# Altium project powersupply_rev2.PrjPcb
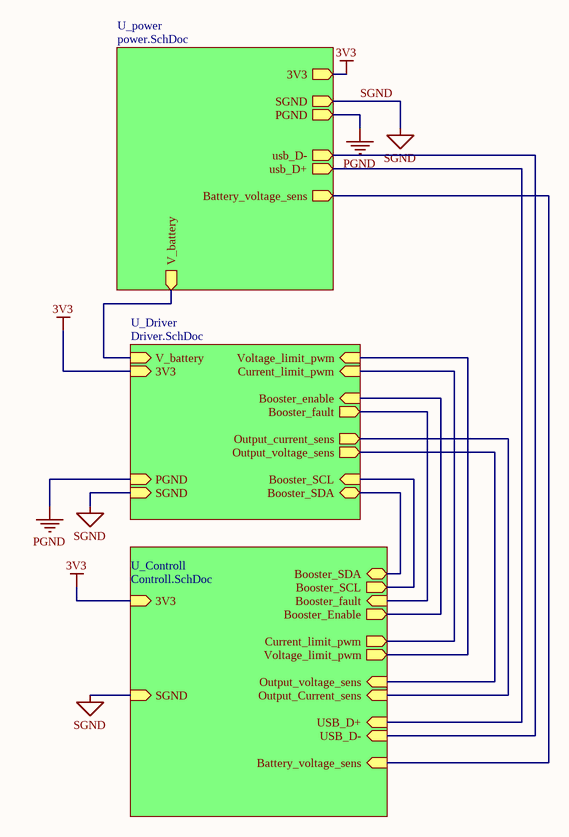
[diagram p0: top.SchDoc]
16 sheets, 137 parts. Net scope: strictly hierarchical (ports join the sheet entries above them; power ports are local).
Board file: PCB1.PcbDoc
Sheets:
  top.SchDoc
    U_power = power.SchDoc
      LDO = LDO.SchDoc
      Battery = battery.SchDoc
      U_usb = usb.SchDoc
      U_usb_isolator = usb_isolator.SchDoc
    U_Driver = Driver.SchDoc
      U_Booster = Booster.SchDoc
      U_linear_regulator = linear_regulator.SchDoc
      pta_current = pwm_to_analog.SchDoc
      pta_voltage = pwm_to_analog_w_gain.SchDoc
    U_Controll = Controll.SchDoc
      U_knobs = knobs.SchDoc
      U_mcu = mcu.SchDoc
      U_Display = Display.SchDoc
      U_programmer = programmer.SchDoc

## Sheet top.SchDoc
size A3

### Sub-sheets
U_Controll = Controll.SchDoc: 3V3 (in), SGND (in), Booster_fault (in), Booster_Enable (out), Voltage_limit_pwm (out), Current_limit_pwm (out), USB_D+ (in), USB_D- (in), Battery_voltage_sens (in), Output_voltage_sens (in), Output_Current_sens (in), Booster_SDA (bidir), Booster_SCL (out)
U_Driver = Driver.SchDoc: V_battery (in), SGND (in), PGND (in), 3V3 (in), Voltage_limit_pwm (in), Current_limit_pwm (in), Booster_enable (in), Output_current_sens (out), Output_voltage_sens (out), Booster_SCL (in), Booster_SDA (bidir), Booster_fault (out)
U_power = power.SchDoc: usb_D- (out), usb_D+ (out), 3V3 (out), SGND (out), PGND (out), V_battery (out), Battery_voltage_sens (out)

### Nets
3V3: sheet U_power/3V3, sheet U_Driver/3V3, sheet U_Controll/3V3
PGND: sheet U_power/PGND, sheet U_Driver/PGND
SGND: sheet U_power/SGND, sheet U_Driver/SGND, sheet U_Controll/SGND
VBAT: sheet U_power/V_battery, sheet U_Driver/V_battery
NetR4_1: sheet U_power/Battery_voltage_sens, sheet U_Controll/Battery_voltage_sens
NetR7_1: sheet U_Driver/Booster_SCL, sheet U_Controll/Booster_SCL
NetR8_1: sheet U_Driver/Booster_SDA, sheet U_Controll/Booster_SDA
NetR9_1: sheet U_Driver/Booster_enable, sheet U_Controll/Booster_Enable
NetR21_1: sheet U_Driver/Current_limit_pwm, sheet U_Controll/Current_limit_pwm
NetR29_2: sheet U_power/usb_D+, sheet U_Controll/USB_D+
NetR31_2: sheet U_power/usb_D-, sheet U_Controll/USB_D-
NetR32_1: sheet U_Driver/Output_voltage_sens, sheet U_Controll/Output_voltage_sens
NetR49_1: sheet U_Driver/Voltage_limit_pwm, sheet U_Controll/Voltage_limit_pwm
NetU1_25: sheet U_Driver/Output_current_sens, sheet U_Controll/Output_Current_sens
NetU1_45: sheet U_Driver/Booster_fault, sheet U_Controll/Booster_fault

## Sheet power.SchDoc
size A3
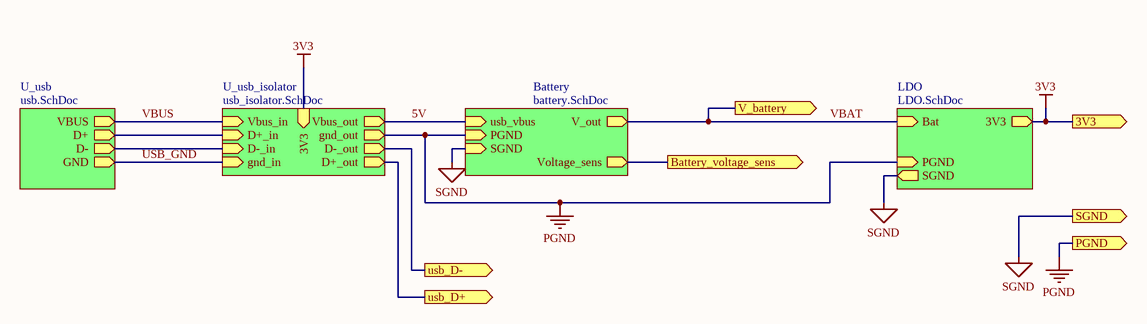
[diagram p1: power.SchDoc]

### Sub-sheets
Battery = battery.SchDoc: V_out (out), Voltage_sens (out), usb_vbus (in), PGND (in), SGND (in)
LDO = LDO.SchDoc: Bat (in), PGND (in), 3V3 (out), SGND (out)
U_usb = usb.SchDoc: VBUS (out), GND (out), D+ (out), D- (out)
U_usb_isolator = usb_isolator.SchDoc: Vbus_in (in), D+_in (in), D-_in (in), gnd_in (in), gnd_out (out), D-_out (out), D+_out (out), Vbus_out (out), 3V3 (in)

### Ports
3V3 (out), Battery_voltage_sens (out), PGND (out), SGND (out), usb_D+ (out), usb_D- (out), V_battery (out)

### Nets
3V3: port 3V3, sheet LDO/3V3, sheet U_usb_isolator/3V3
PGND: port PGND, sheet LDO/PGND, sheet Battery/PGND, sheet U_usb_isolator/gnd_out
SGND: port SGND, sheet LDO/SGND, sheet Battery/SGND
5V: sheet Battery/usb_vbus, sheet U_usb_isolator/Vbus_out
USB_GND: sheet U_usb/GND, sheet U_usb_isolator/gnd_in
VBAT: port V_battery, sheet LDO/Bat, sheet Battery/V_out
VBUS: sheet U_usb/VBUS, sheet U_usb_isolator/Vbus_in
NetJ1_A6: sheet U_usb/D+, sheet U_usb_isolator/D+_in
NetJ1_A7: sheet U_usb/D-, sheet U_usb_isolator/D-_in
NetR4_1: port Battery_voltage_sens, sheet Battery/Voltage_sens
NetR29_2: port usb_D+, sheet U_usb_isolator/D+_out
NetR31_2: port usb_D-, sheet U_usb_isolator/D-_out

## Sheet LDO.SchDoc
size A4
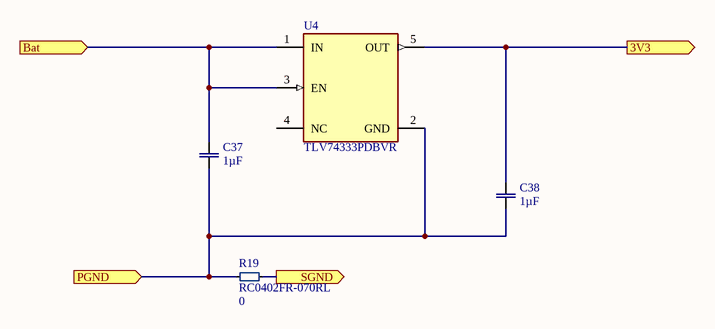
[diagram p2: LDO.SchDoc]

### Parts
C37  Capacitance: 1µF  [CAP0805]  (hidden comment: CL21B105KBFNNNG)
C38  Capacitance: 1µF  [CAP0805]  (hidden comment: CL21B105KBFNNNG)
R19  RC0402FR-070RL  Resistance: 0  [SMD_0402(1005)_M]
U4  TLV74333PDBVR  [FP-DBV0005A-IPC_A]

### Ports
3V3 (out), Bat (in), PGND (in), SGND (out)

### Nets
3V3: C38.2 U4.5(OUT) ; port 3V3
PGND: C37.1 C38.1 R19.1 U4.2(GND) ; port PGND
SGND: R19.2 ; port SGND
VBAT: C37.2 U4.1(IN) U4.3(EN) ; port Bat

Not connected (* = marked no-connect by the designer): U4 4(NC)

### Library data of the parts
C37 C38 = CMP-0001-00012-4: SAMSUNG ELECTRO-MECHANICS - CL21B105KBFNNNG - MLCC CAPACITORS; Voltage Rating: 50V; Dielectric: X7R; Material: Ceramic; Tolerance: 10%
R19 = CMP-0001-00005-6: Res Thick Film 0402 0 Ohm Molded SMD SMD Paper T/R; Value: 0; Temperature Coefficient: 200ppm/°C; Power Rating: 62.5mW; Voltage Rating: 50V; Tolerance: 1%
U4 = CMP-00004-1: 300mA Low-Dropout (LDO) Regulator 5-SOT-23 -40 to 125; Power Supply Rejection Ratio (PSRR): 28dB; Dropout Voltage: 270mV; Min Output Voltage: 3.3V; Output Configuration: Positive; Max Input Voltage: 5.5V; Output Type: Fixed; Number of Regulators: 1; Quiescent Current: 60uA

## Sheet battery.SchDoc
size A4
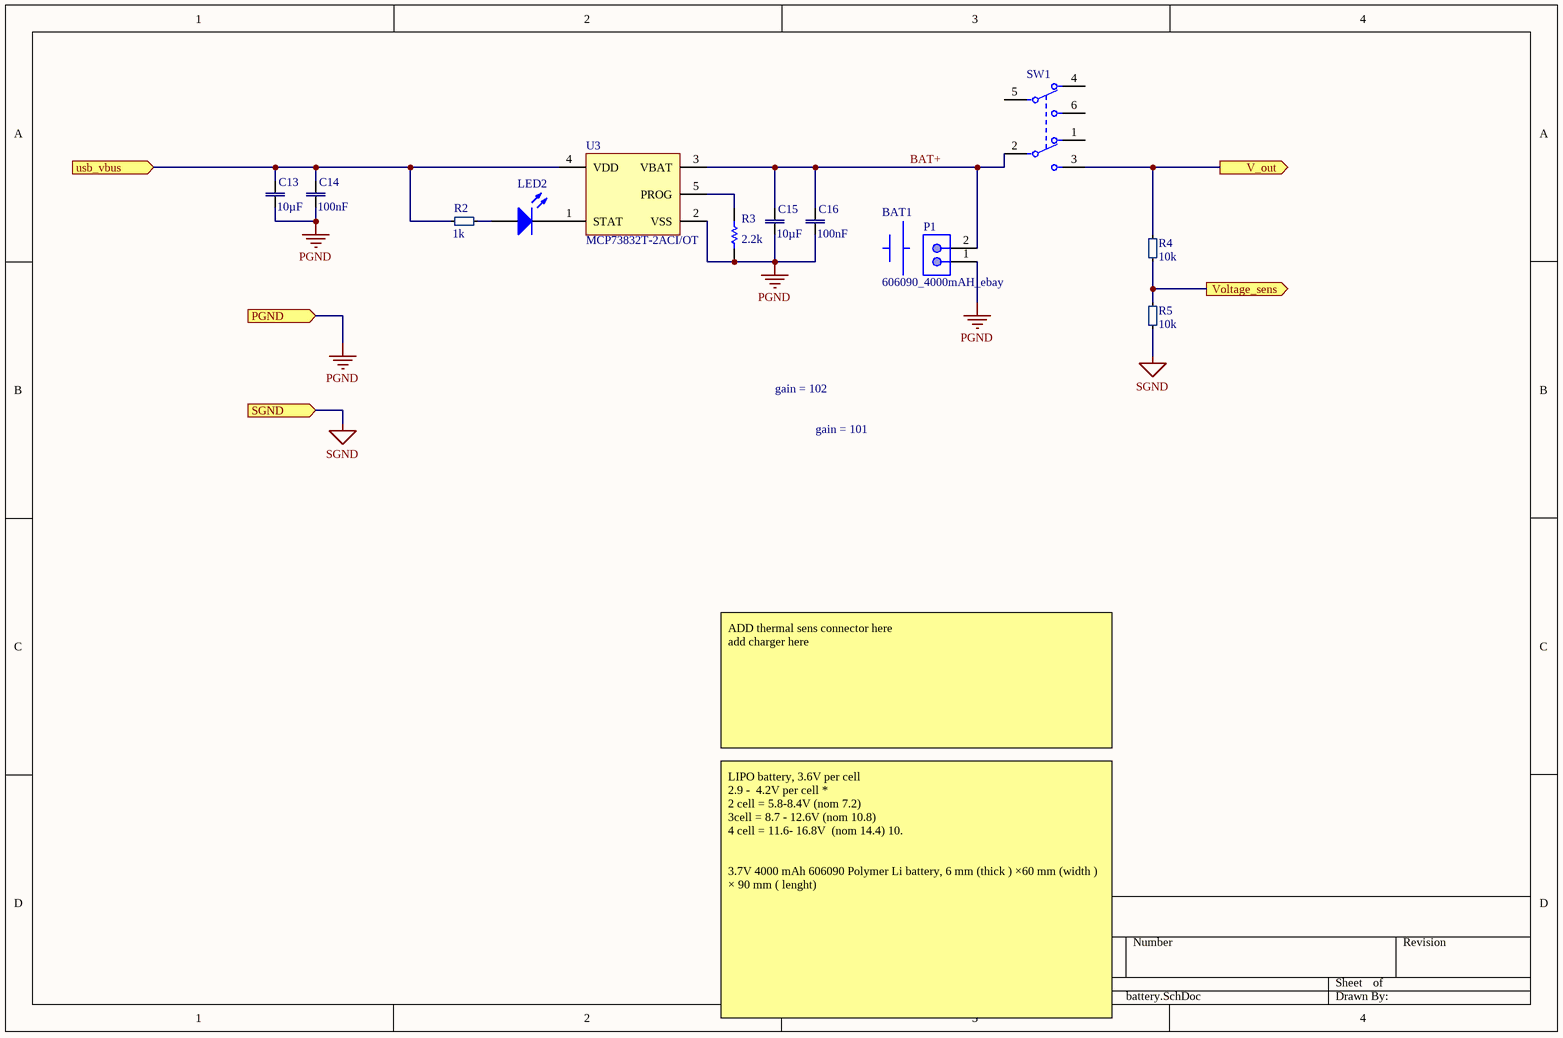
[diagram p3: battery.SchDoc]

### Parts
BAT1  606090_4000mAH_ebay  [606090_4000mAH_ebay-Footprint-1]
C13  Capacitance: 10µF  [Chip2PinSM127P600-8N]  (hidden comment: CL31A106MBHNNNE)
C14  Capacitance: 100nF  [cap0402]  (hidden comment: GRM155R71H104ME14D)
C15  Capacitance: 10µF  [Chip2PinSM127P600-8N]  (hidden comment: CL31A106MBHNNNE)
C16  Capacitance: 100nF  [cap0402]  (hidden comment: GRM155R71H104ME14D)
LED2  150080BS75000  [0805_A]  (value not drawn)
P1  B2B-XH-A(LF)(SN)  [JST-B2B-XH-A_V]  (value not drawn)
R2  Resistance: 1k  [SMD_0402(1005)_M]  (hidden comment: RC0402FR-071KL)
R3  Resistance: 2.2k  [RESC1005X40X25NL05T10]  (hidden comment: RC0402FR-072K2L)
R4  Resistance: 10k  [SMD_0402(1005)_M]  (hidden comment: RC0402FR-0710KL)
R5  Resistance: 10k  [SMD_0402(1005)_M]  (hidden comment: RC0402FR-0710KL)
SW1  100DP1T2B3M2QEH  [FP-100DP1T2B3M2QEH-MFG]  (value not drawn)
U3  MCP73832T-2ACI/OT  [SOT-23-OT5_M]

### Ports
PGND (in), SGND (in), usb_vbus (in), V_out (out), Voltage_sens (out)

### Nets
PGND: C13.1 C14.1 C15.1 C16.1 P1.1 R3.1 U3.2(VSS) ; port PGND
SGND: R5.1 ; port SGND
5V: C13.2 C14.2 R2.2 U3.4(VDD) ; port usb_vbus
BAT+: C15.2 C16.2 P1.2 SW1.2 U3.3(VBAT)
VBAT: R4.2 SW1.3 ; port V_out
NetLED2_1: LED2.1(K) U3.1(STAT)
NetLED2_2: LED2.2(A) R2.1
NetR3_2: R3.2 U3.5(PROG)
NetR4_1: R4.1 R5.2 ; port Voltage_sens

Not connected (* = marked no-connect by the designer): SW1 1 4 5 6

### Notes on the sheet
- gain = 102
- gain = 101
- ADD thermal sens connector here
  add charger here
- LIPO battery, 3.6V per cell
  2.9 -  4.2V per cell *
  2 cell = 5.8-8.4V (nom 7.2)
  3cell = 8.7 - 12.6V (nom 10.8)
  4 cell = 11.6- 16.8V  (nom 14.4) 10.
  3.7V 4000 mAh 606090 Polymer Li battery, 6 mm (thick ) ×60 mm (width ) × 90 mm ( lenght)

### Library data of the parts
BAT1 = CMP-ROOT-00019-4: https://www.ebay.com/itm/3-7V-4000-mAh-606090-Polymer-Li-battery-Li-po-For-PDA-GPS-DVD-ipod-Tablet-PC/182107148013; Voltage: 3.7V
C13 C15 = CMP-0001-00015-2: CAP CER 10UF 50V X5R 1206; Capacitor Type: Ceramic; Tolerance: 20%
C14 C16 = CMP-0001-00001-8: 0402 0.1 uF 50 V ±20% Tolerance X7R SMT Monolithic Ceramic Chip Capacitor; Value: 100nF; Voltage Rating: 50V
LED2 = CMP-00002-1: SMD LED blue 3.5 V 0805, 150080BS75000, Würth Elektronik; Dominant Wavelength: 470nm; Luminous Intensity: 145mcd; Lens Style: Clear,Rectangular; Forward Current: 30mA; Test Current: 20mA; Forward Voltage: 3.2V; Viewing Angle: 140°
P1 = CMP-ROOT-00008-1: Conn Shrouded Header (4 Sides) HDR 2 POS 2.5mm Solder ST Thru-Hole Box; Max Current Rating: 3A; Connector Type: Male Pin; Contact Resistance: 20mR; Max Voltage Rating (DC): 250V; System: Connector; Wire/Cable Gauge: 22AWG; Number of Contacts: 2; Insulation Resistance: 1GR
R2 = CMP-001-0000-7: Surface Mount Chip Resistor, Thick Film, RC Series, 1 kohm, 62.5 mW, 1%, 50 V, 0402 [1005 Metric]; Temperature Coefficient: 100ppm/°C; Value: 1k; Voltage Rating: 50V; Power Rating: 62.5mW
R3 = CMP-001-0020-3: RES SMD 2.2K OHM 1% 1/16W 0402; Temperature Coefficient: 100ppm/°C; Voltage Rating: 50V; Power Rating: 63mW
R4 R5 = CMP-008-0005-9: Surface Mount Thick Film Resistor, Rc Series, 10 Kohm, 62.5 Mw, - 1%, 50 V, 0402 [1005 Metric]; Voltage Rating (DC): 50V; Value: 10k; Temperature Coefficient: 100ppm/°C; Power Rating: 62.5mW
SW1 = CMP-ROOT-00014-1: 100 Series DPDT On-None-On Through Hole Miniature Toggle Switch; Illumination Type: Non-Illuminated; Actuator Type: Standard Round; Switch Function: On-On; Actuator Length: 6.86mm; Voltage Rating (AC): 120V; Actuator Material: Brass,Chrome; Current Rating: 5A; Voltage Rating (DC): 28V; Electrical Life: 40000Cycles
U3 = CMP-006-0003-2: BATTERY CHARGER, 500mA, SOT23-5; Battery Type:Li-Ion, Li-Pol; Input Voltage:6V; Battery Charge Voltage:4.2V; Charge Current Max:500mA; Battery IC Case Style:SOT-23; No. of Pins:5; No. of Series Cells:1; Operating Temperature Max:85 C; Max Supply Voltage: 6V; Number of Cells: 1; Max Output Voltage: 4.5V; Max Power Dissipation: 1.54W; Min Supply Voltage: 3.75V; Min Output Voltage: 4.168V; Output Current: 10mA; Output Voltage: 4.2V

## Sheet usb.SchDoc
size A3
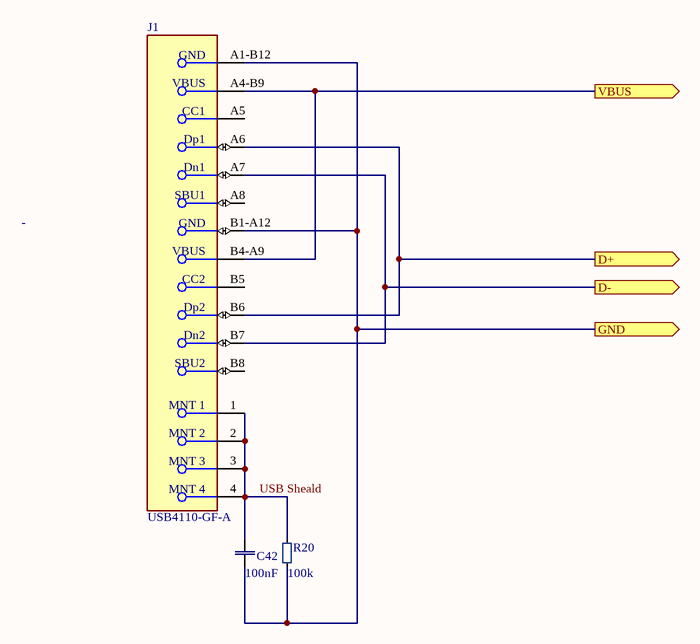
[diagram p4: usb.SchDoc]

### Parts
C42  Capacitance: 100nF  [cap0402]  (hidden comment: GRM155R71H104ME14D)
J1  USB4110-GF-A  [FP-USB4110-GF-A-MFG]
R20  Resistance: 100k  [SMD_0402(1005)_M]  (hidden comment: RC0402FR-07100KL)

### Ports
D+ (out), D- (out), GND (out), VBUS (out)

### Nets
USB Sheald: C42.2 J1.1(MNT_1) J1.2(MNT_2) J1.3(MNT_3) J1.4(MNT_4) R20.2
USB_GND: C42.1 J1.A1-B12(GND) J1.B1-A12(GND) R20.1 ; port GND
VBUS: J1.A4-B9(VBUS) J1.B4-A9(VBUS) ; port VBUS
NetJ1_A6: J1.A6(Dp1) J1.B6(Dp2) ; port D+
NetJ1_A7: J1.A7(Dn1) J1.B7(Dn2) ; port D-

Not connected (* = marked no-connect by the designer): J1 A5(CC1) A8(SBU1) B5(CC2) B8(SBU2)

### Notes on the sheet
- -

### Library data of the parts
C42 = CMP-0001-00001-8: as C14 on sheet battery
J1 = CMP-ROOT-00018-1: Conn Usb 2.0 Type-c R/a SMT; Number of Positions: 12; System: Connector
R20 = CMP-0001-00006-4: Res General Purpose Thick Film 0402 100K Ohm 1% 1/16W ±100ppm/°C Molded SMD Paper T/R; Max Power Dissipation: 63mW; Voltage Rating: 50V

## Sheet usb_isolator.SchDoc
size A3
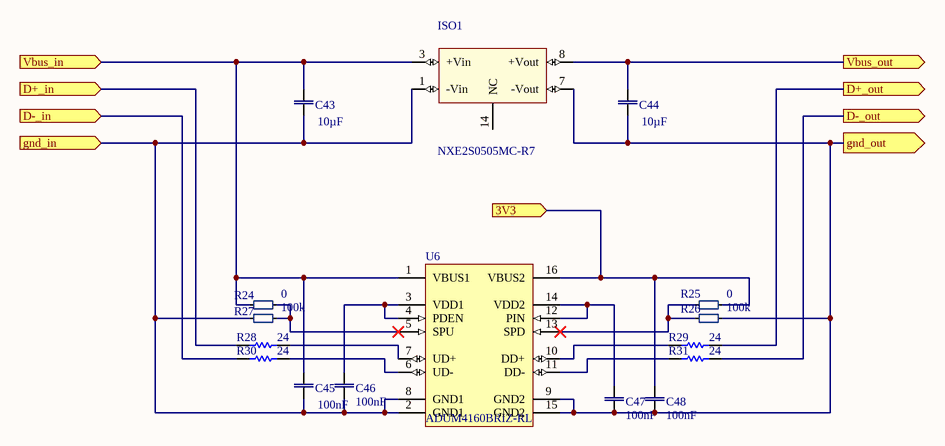
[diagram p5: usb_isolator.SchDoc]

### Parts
C43  Capacitance: 10µF  [Chip2PinSM127P600-8N]  (hidden comment: CL31A106MBHNNNE)
C44  Capacitance: 10µF  [Chip2PinSM127P600-8N]  (hidden comment: CL31A106MBHNNNE)
C45  Capacitance: 100nF  [cap0402]  (hidden comment: GRM155R71H104ME14D)
C46  Capacitance: 100nF  [cap0402]  (hidden comment: GRM155R71H104ME14D)
C47  Capacitance: 100nF  [cap0402]  (hidden comment: GRM155R71H104ME14D)
C48  Capacitance: 100nF  [cap0402]  (hidden comment: GRM155R71H104ME14D)
ISO1  NXE2S0505MC-R7  [NXE2S0505MC-R7-Footprint-1]
R24  Resistance: 0  [SMD_0402(1005)_M]  (hidden comment: RC0402FR-070RL)
R25  Resistance: 0  [SMD_0402(1005)_M]  (hidden comment: RC0402FR-070RL)
R26  Resistance: 100k  [SMD_0402(1005)_M]  (hidden comment: RC0402FR-07100KL)
R27  Resistance: 100k  [SMD_0402(1005)_M]  (hidden comment: RC0402FR-07100KL)
R28  Resistance: 24  [RESC1005X40X25ML05T10]  (hidden comment: RC0402FR-0724RL)
R29  Resistance: 24  [RESC1005X40X25ML05T10]  (hidden comment: RC0402FR-0724RL)
R30  Resistance: 24  [RESC1005X40X25ML05T10]  (hidden comment: RC0402FR-0724RL)
R31  Resistance: 24  [RESC1005X40X25ML05T10]  (hidden comment: RC0402FR-0724RL)
U6  ADUM4160BRIZ-RL  [ADI-RI-16-1_M]

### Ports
3V3 (in), D+_in (in), D+_out (out), D-_in (in), D-_out (out), gnd_in (in), gnd_out (out), Vbus_in (in), Vbus_out (out)

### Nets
3V3: C48.1 R25.2 U6.16(VBUS2) ; port 3V3
PGND: C44.1 C47.2 C48.2 ISO1.7(-Vout) R26.2 U6.9(GND2) U6.15(GND2) ; port gnd_out
5V: C44.2 ISO1.8(+Vout) ; port Vbus_out
USB_GND: C43.1 C45.1 C46.2 ISO1.1(-Vin) R27.1 U6.2(GND1) U6.8(GND1) ; port gnd_in
VBUS: C43.2 C45.2 ISO1.3(+Vin) R24.1 U6.1(VBUS1) ; port Vbus_in
NetC46_1: C46.1 U6.3(VDD1) U6.4(PDEN)
NetC47_1: C47.1 U6.12(PIN) U6.14(VDD2)
NetJ1_A6: R28.1 ; port D+_in
NetJ1_A7: R30.1 ; port D-_in
NetR24_2: R24.2 R27.2 U6.5(SPU)
NetR25_1: R25.1 R26.1 U6.13(SPD)
NetR28_2: R28.2 U6.7(UD+)
NetR29_1: R29.1 U6.10(DD+)
NetR29_2: R29.2 ; port D+_out
NetR30_2: R30.2 U6.6(UD-)
NetR31_1: R31.1 U6.11(DD-)
NetR31_2: R31.2 ; port D-_out

Not connected (* = marked no-connect by the designer): ISO1 14(NC)

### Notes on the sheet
- Select highspeed or lowspeed

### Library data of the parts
C43 C44 = CMP-0001-00015-2: as C13 on sheet battery
C45-C48 = CMP-0001-00001-8: as C14 on sheet battery
ISO1 = CMP-018-0000-2: DC DC CONVERTER 5V 2W; Current - Output 1: 400mA; Min Input Voltage: 4.5V; Max Input Voltage (DC): 5.5V; Efficiency: 72%; Number of Outputs: 1; Isolation Voltage: 3kV
R24 R25 = CMP-0001-00005-6: as R19 on sheet LDO
R26 R27 = CMP-0001-00006-4: Res General Purpose Thick Film 0402 100K Ohm 1% 1/16W ±100ppm/°C Molded SMD Paper T/R; Power Rating: 63mW; Voltage Rating: 50V
R28-R31 = CMP-0001-00017-2: Thick Film Resistors 24 OHM 1%; Voltage Rating: 50V; Temperature Coefficient: 100ppm/°C; Power Rating: 63mW
U6 = CMP-00003-5: Digital Isolator CMOS 4-CH 12Mbps 16-Pin SOIC T/R; Turn-On Delay Time: 60ns; Channel Type: Bidirectional; Isolated Power: No; Min Supply Voltage: 3.1V; Max Supply Voltage: 5.5V; Nominal Supply Current: 6mA; Propagation Delay: 70ns; Number of Channels: 2

## Sheet Driver.SchDoc
size A3
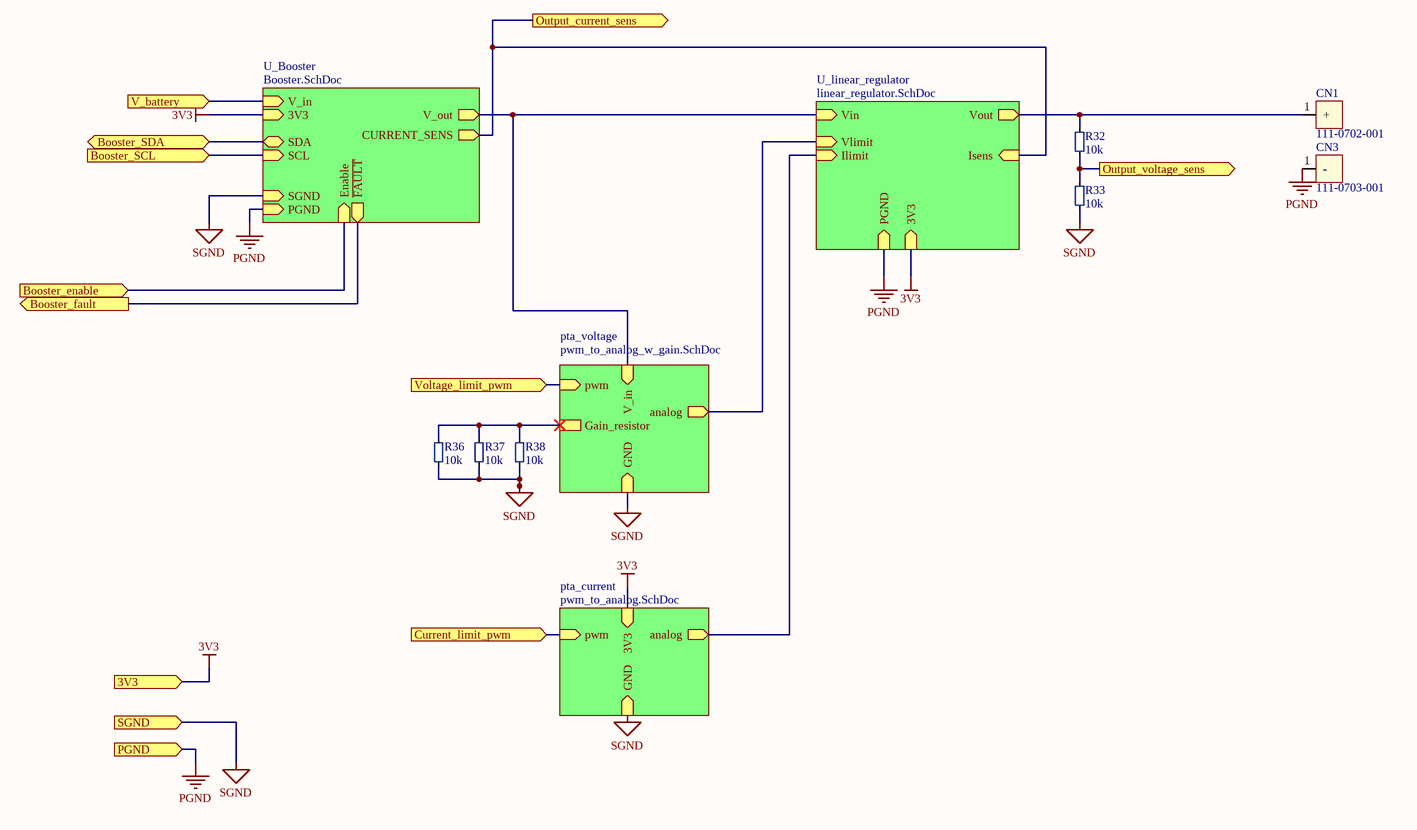
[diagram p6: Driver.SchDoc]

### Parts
CN1  111-0702-001  [111-0702-001-Footprint-1]
CN3  111-0703-001  [111-0702-001-Footprint-1]
R32  Resistance: 10k  [SMD_0402(1005)_M]  (hidden comment: RC0402FR-0710KL)
R33  Resistance: 10k  [SMD_0402(1005)_M]  (hidden comment: RC0402FR-0710KL)
R36  Resistance: 10k  [SMD_0402(1005)_M]  (hidden comment: RC0402FR-0710KL)
R37  Resistance: 10k  [SMD_0402(1005)_M]  (hidden comment: RC0402FR-0710KL)
R38  Resistance: 10k  [SMD_0402(1005)_M]  (hidden comment: RC0402FR-0710KL)

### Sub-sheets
pta_current = pwm_to_analog.SchDoc: pwm (in), analog (out), GND (in), 3V3 (in)
pta_voltage = pwm_to_analog_w_gain.SchDoc: pwm (in), analog (out), GND (in), V_in (in), Gain_resistor
U_Booster = Booster.SchDoc: V_in (in), Enable (in), V_out (out), SGND (in), PGND (in), SCL (in), 3V3 (in), SDA (bidir), CURRENT_SENS (out), ~{FAULT} (out)
U_linear_regulator = linear_regulator.SchDoc: 3V3 (in), PGND (in), Vlimit (in), Ilimit (in), Vin (in), Isens (in), Vout (out)

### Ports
3V3 (in), Booster_enable (in), Booster_fault (out), Booster_SCL (in), Booster_SDA (bidir), Current_limit_pwm (in), Output_current_sens (out), Output_voltage_sens (out), PGND (in), SGND (in), V_battery (in), Voltage_limit_pwm (in)

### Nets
3V3: port 3V3, sheet U_Booster/3V3, sheet U_linear_regulator/3V3, sheet pta_current/3V3
PGND: CN3.1(-) ; port PGND, sheet U_Booster/PGND, sheet U_linear_regulator/PGND
SGND: R33.1 R36.1 R37.1 R38.1 ; port SGND, sheet U_Booster/SGND, sheet pta_current/GND, sheet pta_voltage/GND
VBAT: port V_battery, sheet U_Booster/V_in
NetC49_2: sheet U_Booster/V_out, sheet U_linear_regulator/Vin, sheet pta_voltage/V_in
NetCN1_1: CN1.1(+) R32.2 ; sheet U_linear_regulator/Vout
NetR7_1: port Booster_SCL, sheet U_Booster/SCL
NetR8_1: port Booster_SDA, sheet U_Booster/SDA
NetR9_1: port Booster_enable, sheet U_Booster/Enable
NetR21_1: port Current_limit_pwm, sheet pta_current/pwm
NetR32_1: R32.1 R33.2 ; port Output_voltage_sens
NetR36_2: R36.2 R37.2 R38.2 ; sheet pta_voltage/Gain_resistor
NetR41_2: sheet U_linear_regulator/Vlimit, sheet pta_voltage/analog
NetR49_1: port Voltage_limit_pwm, sheet pta_voltage/pwm
NetU1_25: port Output_current_sens, sheet U_Booster/CURRENT_SENS, sheet U_linear_regulator/Isens
NetU1_45: port Booster_fault, sheet U_Booster/~{FAULT}
NetU2_3: sheet U_linear_regulator/Ilimit, sheet pta_current/analog

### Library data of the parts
CN1 = CMP-003-0000-1: CONN BIND POST KNURLED RED; Body Material: Brass; Current Rating: 15A; System: Connector; Insulation: Insulated; Panel Thickness: 0.313inch; Hole Diameter: 0.086inch; Number of Positions: 1
CN3 = CMP-003-0001-1: CONN BIND POST KNURLED BLACK; Number of Positions: 1; Current Rating: 15A; Insulation: Insulated; Body Material: Brass; Panel Thickness: 0.313inch; Hole Diameter: 0.086inch; System: Connector
R32 R33 R36-R38 = CMP-008-0005-9: Surface Mount Thick Film Resistor, Rc Series, 10 Kohm, 62.5 Mw, - 1%, 50 V, 0402 [1005 Metric]; Voltage Rating: 50V; Power Rating: 62.5mW; Value: 10k; Temperature Coefficient: 100ppm/°C

## Sheet Booster.SchDoc
size A3
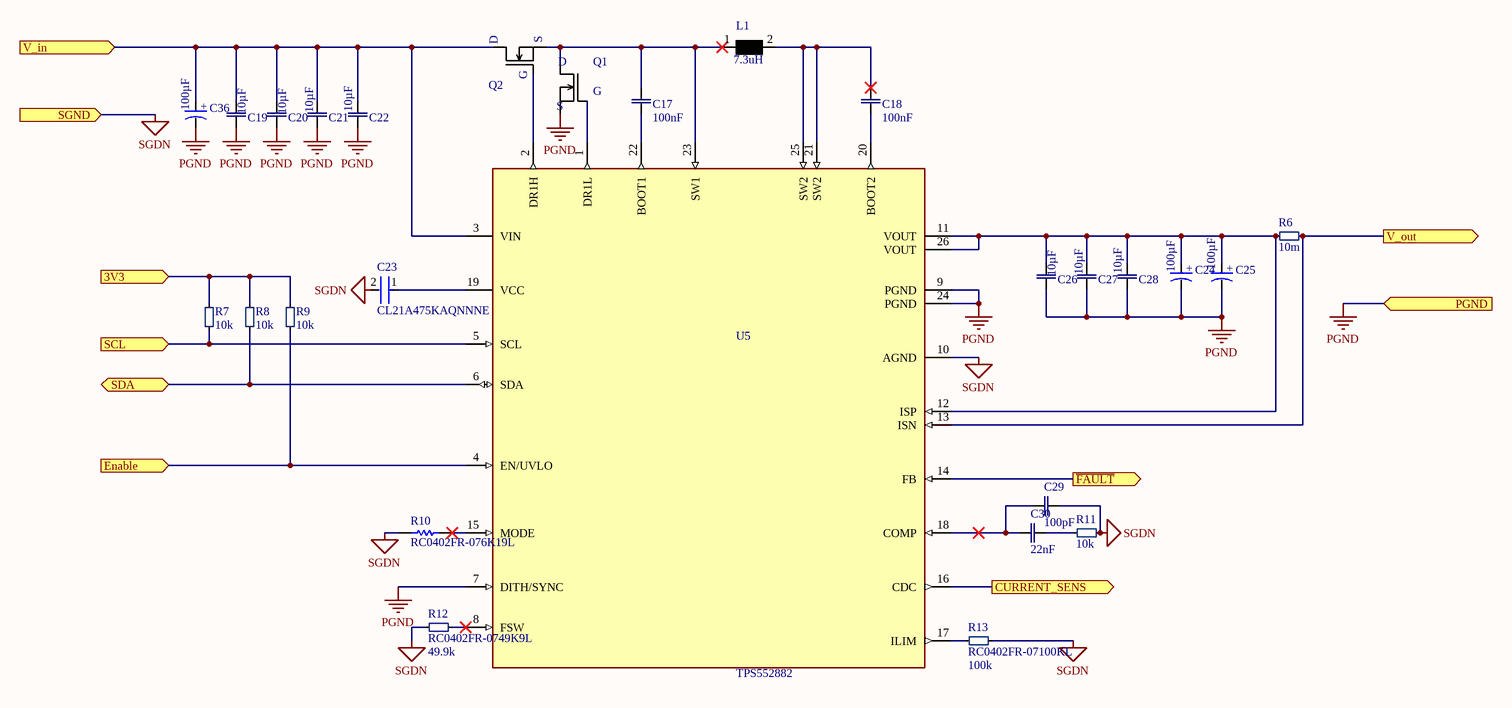
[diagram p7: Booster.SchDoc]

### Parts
C17  value 100nF  [cap0402]  (hidden comment: GRM155R71H104ME14D)
C18  value 100nF  [cap0402]  (hidden comment: GRM155R71H104ME14D)
C19  Capacitance: 10µF  [Chip2PinSM127P600-8N]  (hidden comment: CL31A106MBHNNNE)
C20  Capacitance: 10µF  [Chip2PinSM127P600-8N]  (hidden comment: CL31A106MBHNNNE)
C21  Capacitance: 10µF  [Chip2PinSM127P600-8N]  (hidden comment: CL31A106MBHNNNE)
C22  Capacitance: 10µF  [Chip2PinSM127P600-8N]  (hidden comment: CL31A106MBHNNNE)
C23  CL21A475KAQNNNE  [FP-CL21-IPC_A]
C24  Capacitance: 100µF  [CAPAE9983X102N]  (hidden comment: EEE-1HA101UP)
C25  Capacitance: 100µF  [CAPAE9983X102N]  (hidden comment: EEE-1HA101UP)
C26  Capacitance: 10µF  [Chip2PinSM127P600-8N]  (hidden comment: CL31A106MBHNNNE)
C27  Capacitance: 10µF  [Chip2PinSM127P600-8N]  (hidden comment: CL31A106MBHNNNE)
C28  Capacitance: 10µF  [Chip2PinSM127P600-8N]  (hidden comment: CL31A106MBHNNNE)
C29  Capacitance: 100pF  [cap0402]  (hidden comment: 885012005080)
C30  Capacitance: 22nF  [cap0402]  (hidden comment: CC0402KRX7R9BB223)
C36  Capacitance: 100µF  [CAPAE9983X102N]  (hidden comment: EEE-1HA101UP)
L1  Inductance: 7.3uH  [INDP130128X65N]  (hidden comment: 7443551730)
Q1  PMN55ENEX  [TSOP95P280X110-6N_PMN55ENE]  (value not drawn)
Q2  PMN55ENEX  [TSOP95P280X110-6N_PMN55ENE]  (value not drawn)
R6  Resistance: 10m  [Chip2PinSM127P600-8N]  (hidden comment: CFG0612-FX-R010ELF)
R7  Resistance: 10k  [SMD_0402(1005)_M]  (hidden comment: RC0402FR-0710KL)
R8  Resistance: 10k  [SMD_0402(1005)_M]  (hidden comment: RC0402FR-0710KL)
R9  Resistance: 10k  [SMD_0402(1005)_M]  (hidden comment: RC0402FR-0710KL)
R10  RC0402FR-076K19L  [RESC0402(1005)_M]
R11  Resistance: 10k  [SMD_0402(1005)_M]  (hidden comment: RC0402FR-0710KL)
R12  RC0402FR-0749K9L  Resistance: 49.9k  [SMD_0402(1005)_M]
R13  RC0402FR-07100KL  Resistance: 100k  [SMD_0402(1005)_M]
U5  TPS552882  [FP-RPM0026A-MFG]

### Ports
3V3 (in), CURRENT_SENS (out), Enable (in), PGND (in), SCL (in), SDA (bidir), SGND (in), V_in (in), V_out (out), ~{FAULT} (out)

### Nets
3V3: R7.2 R8.2 R9.2 ; port 3V3
PGND: C19.1 C20.1 C21.1 C22.1 C24.2(-) C25.2(-) C26.1 C27.1 C28.1 C36.2(-) Q1.1(D) U5.7(DITH/SYNC) U5.9(PGND) U5.24(PGND) ; port PGND
SGDN: C23.2 C29.1 R10.1 R11.1 R12.1 R13.2 U5.10(AGND) ; port SGND  [project net SGND]
VBAT: C19.2 C20.2 C21.2 C22.2 C36.1(+) Q2.2(S) U5.3(VIN) ; port V_in
NetC17_1: C17.1 U5.22(BOOT1)
NetC17_2: C17.2 L1.1 Q1.2(S) Q2.1(D) U5.23(SW1)
NetC18_1: C18.1 U5.20(BOOT2)
NetC18_2: C18.2 L1.2 U5.21(SW2) U5.25(SW2)
NetC23_1: C23.1 U5.19(VCC)
NetC24_1: C24.1(+) C25.1(+) C26.2 C27.2 C28.2 R6.2 U5.11(VOUT) U5.12(ISP) U5.26(VOUT)
NetC29_2: C29.2 C30.2 U5.18(COMP)
NetC30_1: C30.1 R11.2
NetC49_2: R6.1 U5.13(ISN) ; port V_out
NetQ1_3: Q1.3(G) U5.1(DR1L)
NetQ2_3: Q2.3(G) U5.2(DR1H)
NetR7_1: R7.1 U5.5(SCL) ; port SCL
NetR8_1: R8.1 U5.6(SDA) ; port SDA
NetR9_1: R9.1 U5.4(EN/UVLO) ; port Enable
NetR10_2: R10.2 U5.15(MODE)
NetR12_2: R12.2 U5.8(FSW)
NetR13_1: R13.1 U5.17(ILIM)
NetU1_25: U5.16(CDC) ; port CURRENT_SENS
NetU1_45: U5.14(FB) ; port ~{FAULT}

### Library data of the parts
C17 C18 = CMP-0001-00001-8: 0402 0.1 uF 50 V ±20% Tolerance X7R SMT Monolithic Ceramic Chip Capacitor; Voltage Rating: 50V
C19-C22 C26-C28 = CMP-0001-00015-2: as C13 on sheet battery
C23 = CMP-0001-00018-1: SAMSUNG ELECTRO-MECHANICS - CL21A475KAQNNNE - SMD Multilayer Ceramic Capacitor, 4.7 µF, 25 V, 0805 [2012 Metric], ± 10%, X5R, CL Series; Voltage Rating: 25V; Capacitance: 4.7µF
C24 C25 C36 = CMP-0001-00014-2: Cap Aluminum 100uF 50V 20% (8 X 10.2mm) SMD 200mA 2000 hr 85C T/R; Capacitor Type: Ceramic; Life (Hours): 2000Hour
C29 = CMP-0001-00010-3: Cap, Mlcc, C0g, 100Pf, 100V, 0402; Capacitor Type: Ceramic; Tolerance: 5%
C30 = CMP-0001-00011-3: Multilayer Ceramic Capacitors MLCC - SMD/SMT 22K pF 10% 50 Volts; Dielectric: X7R; Voltage Rating (DC): 50V
L1 = CMP-ROOT-00003-1: WURTH ELEKTRONIK         7443551730             Surface Mount Power Inductor, WE-HCI Series, 7.3 H, 13 A, 12 A, Shielded, 5900 ohm; Tolerance: 20%; Max DC Current: 13A; DC Resistance (DCR): 5.9mR; Saturation Current: 12A; Series Resistance: 5.9R; Test Frequency: 100kHz; Self Resonant Frequency: 28MHz
Q1 Q2 = CMP-ROOT-00001-4: MOSFET N-CH 60V 4.5A 6TSOP; Input Capacitance: 646pF; Max Power Dissipation: 6.25mW; Rds On Max: 60mR
R6 = CMP-0001-00016-1: BOURNS JW MILLER - CFG0612-FX-R010ELF - SMD Current Sense Resistor, 0.01 ohm, CFG Series, 1206 Wide, 1 W, ± 1%, Metal Foil
R7-R9 = CMP-008-0005-9: Surface Mount Thick Film Resistor, Rc Series, 10 Kohm, 62.5 Mw, - 1%, 50 V, 0402 [1005 Metric]; Voltage Rating: 50V; Temperature Coefficient: 100ppm/°C; Power Rating: 62.5mW; Value: 10k
R10 = CMP-0001-00019-2: RES SMD 6.19K OHM 1% 1/16W 0402; Power Rating: 62.5mW; Temperature Coefficient: 100ppm/°C; Voltage Rating: 50V
R11 = CMP-008-0005-9: as R4 on sheet battery
R12 = CMP-0001-00013-2: Res Thick Film 0402 49.9K Ohm 1% 0.063W(1/16W) ±100ppm/C Epoxy Pad SMD T/R; Power Rating: 62.5mW; Voltage Rating: 50V; Temperature Coefficient: 100ppm/°C
R13 = CMP-0001-00006-4: as R20 on sheet usb
U5 = CMP-00006-4: 36V, 16A buck-boost converter with PPS control

## Sheet linear_regulator.SchDoc
size A3
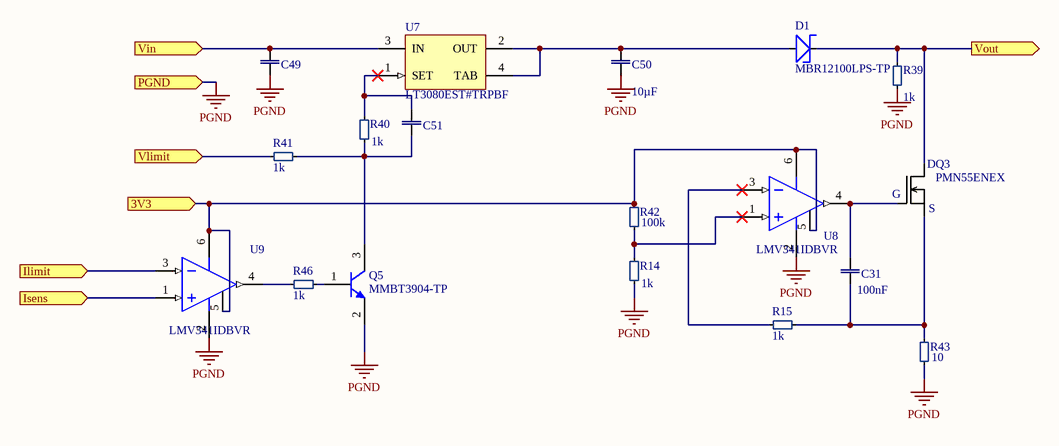
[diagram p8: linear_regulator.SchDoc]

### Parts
C31  Capacitance: 100nF  [cap0402]  (hidden comment: GRM155R71H104ME14D)
C49  CL21B105KBFNNNG  [CAP0805]  (value not drawn)
C50  Capacitance: 10µF  [Chip2PinSM127P600-8N]  (hidden comment: CL31A106MBHNNNE)
C51  CL21B105KBFNNNG  [CAP0805]  (value not drawn)
D1  MBR12100LPS-TP  [DFN445P552X120-3N]
Q3  PMN55ENEX  [TSOP95P280X110-6N_PMN55ENE]
Q5  MMBT3904-TP  [ONSC-SOT-23-3-318-08_V]
R14  Resistance: 1k  [SMD_0402(1005)_M]  (hidden comment: RC0402FR-071KL)
R15  Resistance: 1k  [SMD_0402(1005)_M]  (hidden comment: RC0402FR-071KL)
R39  Resistance: 1k  [SMD_0402(1005)_M]  (hidden comment: RC0402FR-071KL)
R40  Resistance: 1k  [SMD_0402(1005)_M]  (hidden comment: RC0402FR-071KL)
R41  Resistance: 1k  [SMD_0402(1005)_M]  (hidden comment: RC0402FR-071KL)
R42  Resistance: 100k  [SMD_0402(1005)_M]  (hidden comment: RC0402FR-07100KL)
R43  Resistance: 10  [SMD_0402(1005)_M]  (hidden comment: RC0402FR-0710RL)
R46  Resistance: 1k  [SMD_0402(1005)_M]  (hidden comment: RC0402FR-071KL)
U7  LT3080EST#TRPBF  [LT-ST-3-SOT-223_M]
U8  LMV341IDBVR  [SOT95P280X145-6N]
U9  LMV341IDBVR  [SOT95P280X145-6N]

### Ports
3V3 (in), Ilimit (in), Isens (in), PGND (in), Vin (in), Vlimit (in), Vout (out)

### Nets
3V3: R42.2 U8.5(!SHDN) U8.6(VCC) U9.5(!SHDN) U9.6(VCC) ; port 3V3
PGND: C49.1 C50.1 Q5.2(E) R14.1 R39.1 R43.1 U8.2(VEE/GND) U9.2(VEE/GND) ; port PGND
NetC31_1: C31.1 Q3.1(D) R15.1 R43.2
NetC31_2: C31.2 Q3.3(G) U8.4(OUT1)
NetC49_2: C49.2 U7.3(IN) ; port Vin
NetC50_2: C50.2 D1.2(A) U7.2(OUT) U7.4(TAB)
NetC51_1: C51.1 Q5.3(C) R40.1 R41.1
NetC51_2: C51.2 R40.2 U7.1(SET)
NetCN1_1: D1.1(K) Q3.2(S) R39.2 ; port Vout
NetQ5_1: Q5.1(B) R46.1
NetR14_2: R14.2 R42.1 U8.1(IN1+)
NetR15_2: R15.2 U8.3(IN1-)
NetR41_2: R41.2 ; port Vlimit
NetR46_2: R46.2 U9.4(OUT1)
NetU1_25: U9.1(IN1+) ; port Isens
NetU2_3: U9.3(IN1-) ; port Ilimit

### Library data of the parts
C31 = CMP-0001-00001-8: as C14 on sheet battery
C49 C51 = CMP-0001-00012-4: SAMSUNG ELECTRO-MECHANICS - CL21B105KBFNNNG - MLCC CAPACITORS; Voltage Rating: 50V; Dielectric: X7R; Material: Ceramic; Capacitance: 1µF; Tolerance: 10%
C50 = CMP-0001-00015-2: as C13 on sheet battery
D1 = CMP-ROOT-00021-1: Diode Schottky 100V 12A TO277B
Q3 = CMP-ROOT-00001-4: MOSFET N-CH 60V 4.5A 6TSOP; Input Capacitance: 646pF; Rds On Max: 60mR; Max Power Dissipation: 6.25mW
Q5 = CMP-014-0001-1: TRANS NPN 40V 0.2A SOT23; Frequency: 300MHz; Emitter Base Voltage (VEBO): 6V; Number of Elements: 1; Max Collector Current: 200mA; Power Dissipation: 350mW; Collector Emitter Saturation Voltage: 300mV; Element Configuration: Single; Collector Base Voltage (VCBO): 60V; hFE Min: 40; Current Rating: 100mA
R14 R15 R39-R41 R46 = CMP-001-0000-7: as R2 on sheet battery
R42 = CMP-0001-00006-4: as R20 on sheet usb
R43 = CMP-0001-00007-3: RES SMD 10 OHM 1% 1/16W 0402; Temperature Coefficient: 100ppm/°C; Value: 10; Voltage Rating: 50V; Power Rating: 63mW
U7 = CMP-00005-1: IC REG LIN POS ADJ 1.1A SOT223-3; Operating Supply Current: 300uA; Quiescent Current: 500uA; Number of Regulators: 1; Output Voltage Accuracy: 1%; Min Input Voltage: 1.2V; Polarity: Positive; Dropout Voltage: 1.35V; Output Voltage: 36V
U8 U9 = CMP-ROOT-00000-2: Single Rail-To-Rail Output CMOS Operational Amplifier with Shutdown 6-SOT-23 -40 to 125; Voltage Gain: 116dB; Output Current: 32mA; Number of Channels: 1; Common Mode Rejection Ratio: 56dB; Input Offset Voltage (Vos): 250uV; Bandwidth: 1MHz; Max Supply Voltage: 5.5V; Max Frequency: 1kHz; Output Current per Channel: 113mA; Operating Supply Current: 107uA; Slew Rate: 1V/µs; Input Bias Current: 200pA; Nominal Supply Current: 170uA; Min Supply Voltage: 2.5V

## Sheet pwm_to_analog.SchDoc
size A4
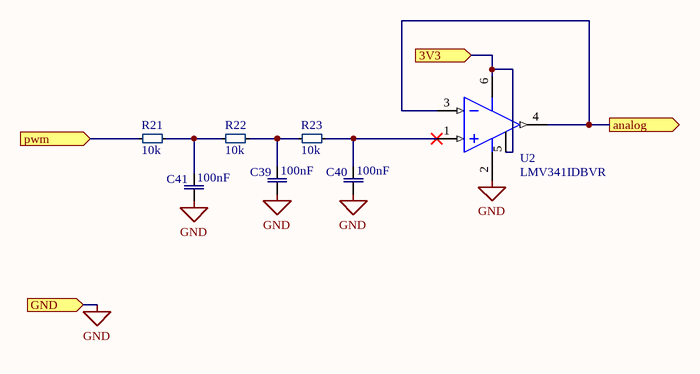
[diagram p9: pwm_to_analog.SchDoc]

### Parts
C39  value 100nF  [cap0402]  (hidden comment: GRM155R71H104ME14D)
C40  value 100nF  [cap0402]  (hidden comment: GRM155R71H104ME14D)
C41  value 100nF  [cap0402]  (hidden comment: GRM155R71H104ME14D)
R21  Resistance: 10k  [SMD_0402(1005)_M]  (hidden comment: RC0402FR-0710KL)
R22  Resistance: 10k  [SMD_0402(1005)_M]  (hidden comment: RC0402FR-0710KL)
R23  Resistance: 10k  [SMD_0402(1005)_M]  (hidden comment: RC0402FR-0710KL)
U2  LMV341IDBVR  [SOT95P280X145-6N]

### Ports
3V3 (in), analog (out), GND (in), pwm (in)

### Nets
3V3: U2.5(!SHDN) U2.6(VCC) ; port 3V3
GND: C39.1 C40.1 C41.1 U2.2(VEE/GND) ; port GND  [project net SGND]
NetC39_2: C39.2 R22.2 R23.1
NetC40_2: C40.2 R23.2 U2.1(IN1+)
NetC41_2: C41.2 R21.2 R22.1
NetR21_1: R21.1 ; port pwm
NetU2_3: U2.3(IN1-) U2.4(OUT1) ; port analog

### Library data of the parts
C39-C41 = CMP-0001-00001-8: as C17 on sheet Booster
R21-R23 = CMP-008-0005-9: as R7 on sheet Booster
U2 = CMP-ROOT-00000-2: as U8 on sheet linear_regulator

## Sheet pwm_to_analog_w_gain.SchDoc
size A4
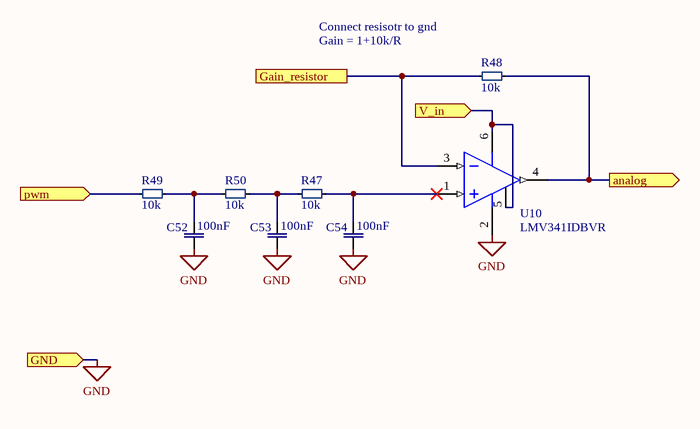
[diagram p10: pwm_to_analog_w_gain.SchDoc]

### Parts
C52  value 100nF  [cap0402]  (hidden comment: GRM155R71H104ME14D)
C53  value 100nF  [cap0402]  (hidden comment: GRM155R71H104ME14D)
C54  value 100nF  [cap0402]  (hidden comment: GRM155R71H104ME14D)
R47  Resistance: 10k  [SMD_0402(1005)_M]  (hidden comment: RC0402FR-0710KL)
R48  Resistance: 10k  [SMD_0402(1005)_M]  (hidden comment: RC0402FR-0710KL)
R49  Resistance: 10k  [SMD_0402(1005)_M]  (hidden comment: RC0402FR-0710KL)
R50  Resistance: 10k  [SMD_0402(1005)_M]  (hidden comment: RC0402FR-0710KL)
U10  LMV341IDBVR  [SOT95P280X145-6N]

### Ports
analog (out), Gain_resistor, GND (in), pwm (in), V_in (in)

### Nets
GND: C52.1 C53.1 C54.1 U10.2(VEE/GND) ; port GND  [project net SGND]
NetC49_2: U10.5(!SHDN) U10.6(VCC) ; port V_in
NetC52_2: C52.2 R49.2 R50.1
NetC53_2: C53.2 R47.1 R50.2
NetC54_2: C54.2 R47.2 U10.1(IN1+)
NetR36_2: R48.1 U10.3(IN1-) ; port Gain_resistor
NetR41_2: R48.2 U10.4(OUT1) ; port analog
NetR49_1: R49.1 ; port pwm

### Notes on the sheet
- (near R48) Connect resisotr to gnd
- Gain = 1+10k/R

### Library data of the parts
C52-C54 = CMP-0001-00001-8: as C17 on sheet Booster
R47-R50 = CMP-008-0005-9: as R7 on sheet Booster
U10 = CMP-ROOT-00000-2: as U8 on sheet linear_regulator

## Sheet Controll.SchDoc
size A3
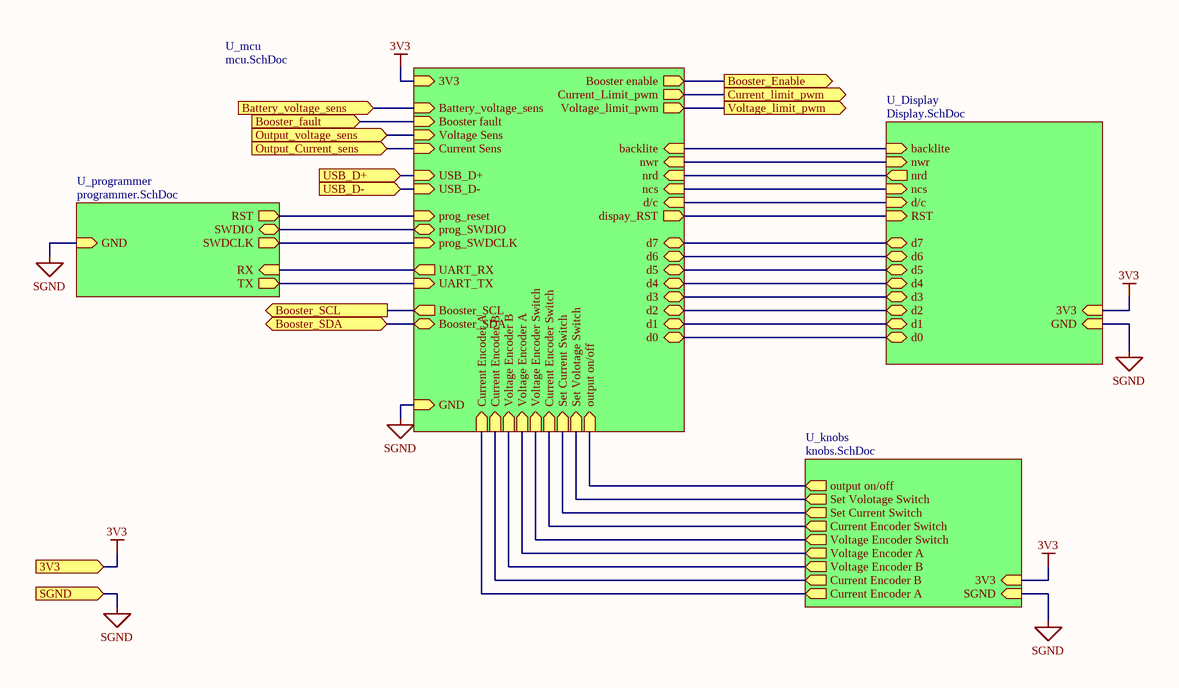
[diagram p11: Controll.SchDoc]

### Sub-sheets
U_Display = Display.SchDoc: d0 (bidir), d4 (bidir), d2 (bidir), d1 (bidir), nwr (in), d/c (in), 3V3 (in), ncs (in), d5 (bidir), d6 (bidir), GND (in), d3 (bidir), d7 (bidir), backlite (in), nrd (out), RST (in)
U_knobs = knobs.SchDoc: Current Encoder A (out), Current Encoder B (out), Voltage Encoder B (out), Voltage Encoder A (out), Voltage Encoder Switch (out), Current Encoder Switch (out), Set Current Switch (out), Set Volotage Switch (out), SGND (in), output on/off (out), 3V3 (in)
U_mcu = mcu.SchDoc: 3V3 (in), GND (in), Battery_voltage_sens (in), Booster enable (out), Booster fault (in), Current_Limit_pwm (out), Voltage_limit_pwm (out), Voltage Sens (in), Current Sens (in), USB_D+ (in), USB_D- (in), nwr (in), d/c (in), ncs (in), nrd (in), backlite (in), d0 (bidir), d4 (bidir), d2 (bidir), d1 (bidir), d5 (bidir), d6 (bidir), d3 (bidir), d7 (bidir), prog_reset (in), prog_SWDIO (bidir), prog_SWDCLK (in), Voltage Encoder B (in), Current Encoder A (in), Voltage Encoder A (in), Current Encoder B (in), Current Encoder Switch (in), Set Volotage Switch (in), Voltage Encoder Switch (in), Set Current Switch (in), UART_RX (out), UART_TX (in), dispay_RST (out), output on/off (in), Booster_SDA (bidir), Booster_SCL (out)
U_programmer = programmer.SchDoc: SWDCLK (out), GND (in), RST (out), SWDIO (bidir), TX (out), RX (in)

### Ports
3V3 (in), Battery_voltage_sens (in), Booster_Enable (out), Booster_fault (in), Booster_SCL (out), Booster_SDA (bidir), Current_limit_pwm (out), Output_Current_sens (in), Output_voltage_sens (in), SGND (in), USB_D+ (in), USB_D- (in), Voltage_limit_pwm (out)

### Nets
3V3: port 3V3, sheet U_knobs/3V3, sheet U_mcu/3V3, sheet U_Display/3V3
SGND: port SGND, sheet U_knobs/SGND, sheet U_mcu/GND, sheet U_Display/GND, sheet U_programmer/GND
NetC32_2: sheet U_knobs/Current Encoder A, sheet U_mcu/Current Encoder A
NetC33_1: sheet U_knobs/Current Encoder B, sheet U_mcu/Current Encoder B
NetC34_2: sheet U_knobs/Voltage Encoder A, sheet U_mcu/Voltage Encoder A
NetC35_1: sheet U_knobs/Voltage Encoder B, sheet U_mcu/Voltage Encoder B
NetCN2_1: sheet U_mcu/prog_SWDIO, sheet U_programmer/SWDIO
NetCN2_2: sheet U_mcu/prog_SWDCLK, sheet U_programmer/SWDCLK
NetCN2_3: sheet U_mcu/prog_reset, sheet U_programmer/RST
NetCN2_6: sheet U_mcu/UART_TX, sheet U_programmer/TX
NetCN2_7: sheet U_mcu/UART_RX, sheet U_programmer/RX
NetDisplay1_23: sheet U_mcu/ncs, sheet U_Display/ncs
NetDisplay1_24: sheet U_mcu/d/c, sheet U_Display/d/c
NetDisplay1_25: sheet U_mcu/nwr, sheet U_Display/nwr
NetDisplay1_26: sheet U_mcu/nrd, sheet U_Display/nrd
NetDisplay1_27: sheet U_mcu/dispay_RST, sheet U_Display/RST
NetDisplay1_28: sheet U_mcu/backlite, sheet U_Display/backlite
NetDisplay1_33: sheet U_mcu/d0, sheet U_Display/d0
NetDisplay1_34: sheet U_mcu/d1, sheet U_Display/d1
NetDisplay1_35: sheet U_mcu/d2, sheet U_Display/d2
NetDisplay1_36: sheet U_mcu/d3, sheet U_Display/d3
NetDisplay1_37: sheet U_mcu/d4, sheet U_Display/d4
NetDisplay1_38: sheet U_mcu/d5, sheet U_Display/d5
NetDisplay1_39: sheet U_mcu/d6, sheet U_Display/d6
NetDisplay1_40: sheet U_mcu/d7, sheet U_Display/d7
NetR4_1: port Battery_voltage_sens, sheet U_mcu/Battery_voltage_sens
NetR7_1: port Booster_SCL, sheet U_mcu/Booster_SCL
NetR8_1: port Booster_SDA, sheet U_mcu/Booster_SDA
NetR9_1: port Booster_Enable, sheet U_mcu/Booster enable
NetR21_1: port Current_limit_pwm, sheet U_mcu/Current_Limit_pwm
NetR29_2: port USB_D+, sheet U_mcu/USB_D+
NetR31_2: port USB_D-, sheet U_mcu/USB_D-
NetR32_1: port Output_voltage_sens, sheet U_mcu/Voltage Sens
NetR49_1: port Voltage_limit_pwm, sheet U_mcu/Voltage_limit_pwm
NetSW2_1: sheet U_knobs/Current Encoder Switch, sheet U_mcu/Current Encoder Switch
NetSW3_1: sheet U_knobs/Set Current Switch, sheet U_mcu/Set Current Switch
NetSW4_1: sheet U_knobs/Voltage Encoder Switch, sheet U_mcu/Voltage Encoder Switch
NetSW5_1: sheet U_knobs/Set Volotage Switch, sheet U_mcu/Set Volotage Switch
NetSW6_1: sheet U_knobs/output on/off, sheet U_mcu/output on/off
NetU1_25: port Output_Current_sens, sheet U_mcu/Current Sens
NetU1_45: port Booster_fault, sheet U_mcu/Booster fault

## Sheet knobs.SchDoc
size A3
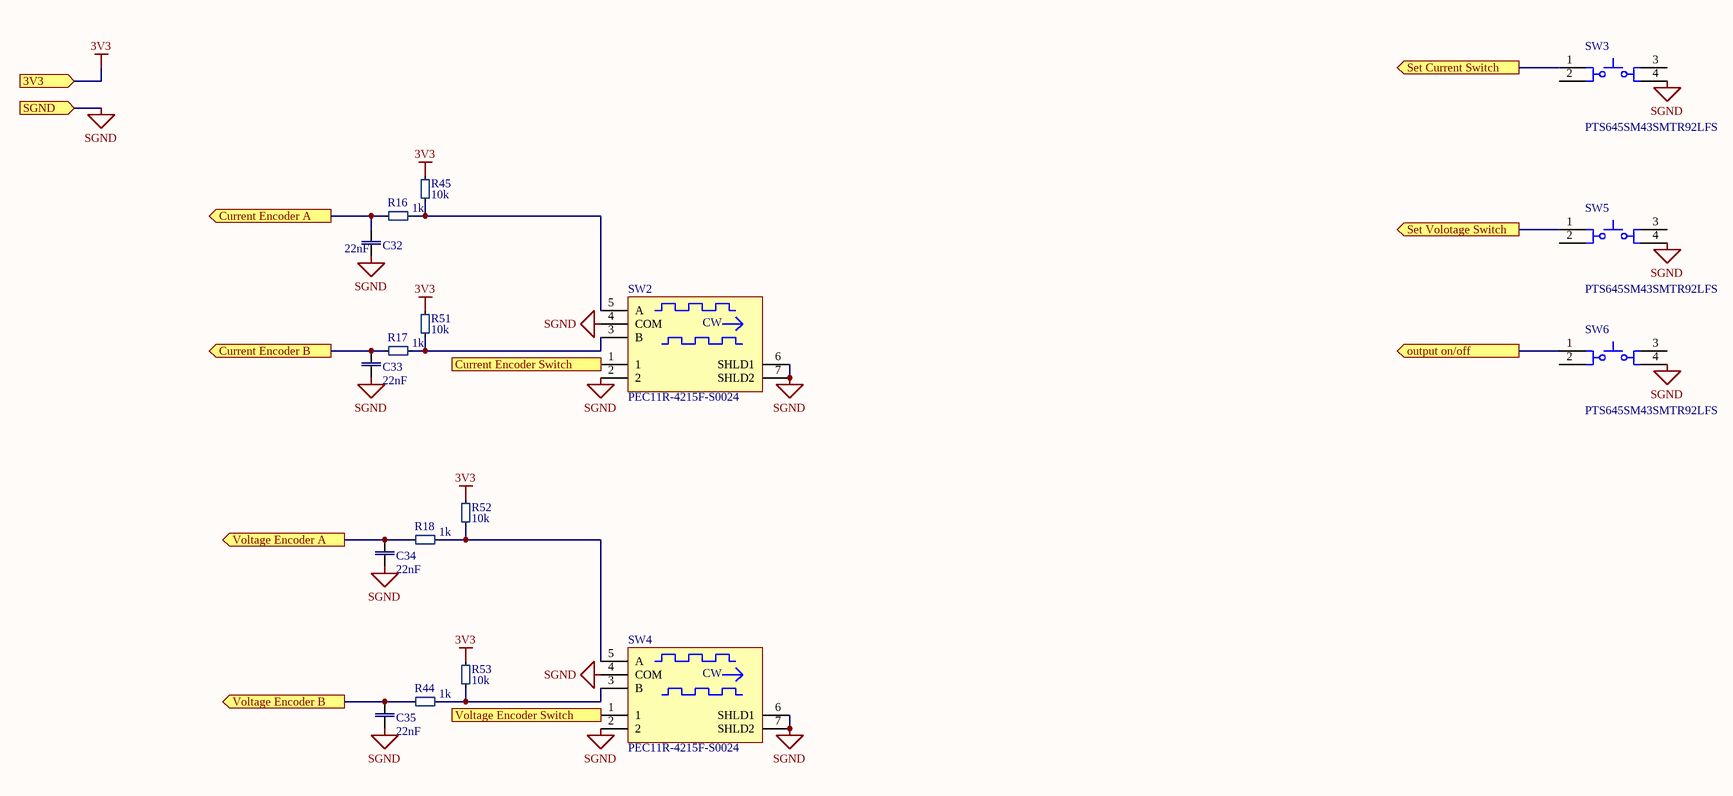
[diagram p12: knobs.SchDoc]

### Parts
C32  Capacitance: 22nF  [cap0402]  (hidden comment: CC0402KRX7R9BB223)
C33  Capacitance: 22nF  [cap0402]  (hidden comment: CC0402KRX7R9BB223)
C34  Capacitance: 22nF  [cap0402]  (hidden comment: CC0402KRX7R9BB223)
C35  Capacitance: 22nF  [cap0402]  (hidden comment: CC0402KRX7R9BB223)
R16  Resistance: 1k  [SMD_0402(1005)_M]  (hidden comment: RC0402FR-071KL)
R17  Resistance: 1k  [SMD_0402(1005)_M]  (hidden comment: RC0402FR-071KL)
R18  Resistance: 1k  [SMD_0402(1005)_M]  (hidden comment: RC0402FR-071KL)
R44  Resistance: 1k  [SMD_0402(1005)_M]  (hidden comment: RC0402FR-071KL)
R45  Resistance: 10k  [SMD_0402(1005)_M]  (hidden comment: RC0402FR-0710KL)
R51  Resistance: 10k  [SMD_0402(1005)_M]  (hidden comment: RC0402FR-0710KL)
R52  Resistance: 10k  [SMD_0402(1005)_M]  (hidden comment: RC0402FR-0710KL)
R53  Resistance: 10k  [SMD_0402(1005)_M]  (hidden comment: RC0402FR-0710KL)
SW2  PEC11R-4215F-S0024  [BOUR-PEC11R-4XXXF-SXXXX_V]
SW3  PTS645SM43SMTR92LFS  [CKCP-PTS645S_V]
SW4  PEC11R-4215F-S0024  [BOUR-PEC11R-4XXXF-SXXXX_V]
SW5  PTS645SM43SMTR92LFS  [CKCP-PTS645S_V]
SW6  PTS645SM43SMTR92LFS  [CKCP-PTS645S_V]

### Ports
3V3 (in), Current Encoder A (out), Current Encoder B (out), Current Encoder Switch (out), output on/off (out), Set Current Switch (out), Set Volotage Switch (out), SGND (in), Voltage Encoder A (out), Voltage Encoder B (out), Voltage Encoder Switch (out)

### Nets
3V3: R45.2 R51.2 R52.2 R53.2 ; port 3V3
SGND: C32.1 C33.2 C34.1 C35.2 SW2.2 SW2.4(COM) SW2.6(SHLD1) SW2.7(SHLD2) SW3.4 SW4.2 SW4.4(COM) SW4.6(SHLD1) SW4.7(SHLD2) SW5.4 SW6.4 ; port SGND
NetC32_2: C32.2 R16.1 ; port Current Encoder A
NetC33_1: C33.1 R17.1 ; port Current Encoder B
NetC34_2: C34.2 R18.1 ; port Voltage Encoder A
NetC35_1: C35.1 R44.1 ; port Voltage Encoder B
NetR16_2: R16.2 R45.1 SW2.5(A)
NetR17_2: R17.2 R51.1 SW2.3(B)
NetR18_2: R18.2 R52.1 SW4.5(A)
NetR44_2: R44.2 R53.1 SW4.3(B)
NetSW2_1: SW2.1 ; port Current Encoder Switch
NetSW3_1: SW3.1 ; port Set Current Switch
NetSW4_1: SW4.1 ; port Voltage Encoder Switch
NetSW5_1: SW5.1 ; port Set Volotage Switch
NetSW6_1: SW6.1 ; port output on/off

Not connected (* = marked no-connect by the designer): SW3 2 3; SW5 2 3; SW6 2 3

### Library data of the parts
C32-C35 = CMP-0001-00011-3: Multilayer Ceramic Capacitors MLCC - SMD/SMT 22K pF 10% 50 Volts; Dielectric: X7R; Voltage Rating: 50V
R16-R18 R44 = CMP-001-0000-7: as R2 on sheet battery
R45 R51-R53 = CMP-008-0005-9: as R32 on sheet Driver
SW2 SW4 = CMP-ROOT-00012-1: BOURNS - PEC11R-4215F-S0024 - Rotary Encoder, Mechanical, Incremental, 24 PPR, 24 Detents, Vertical, With Momentary Push Switch; Hole Diameter: 1.8mm; Detent: Yes; Pulses per Revolution: 24; Output Type: Quadrature,Incremental; Number of Channels: 2
SW3 SW5 SW6 = CMP-ROOT-00020-1

## Sheet mcu.SchDoc
size A3
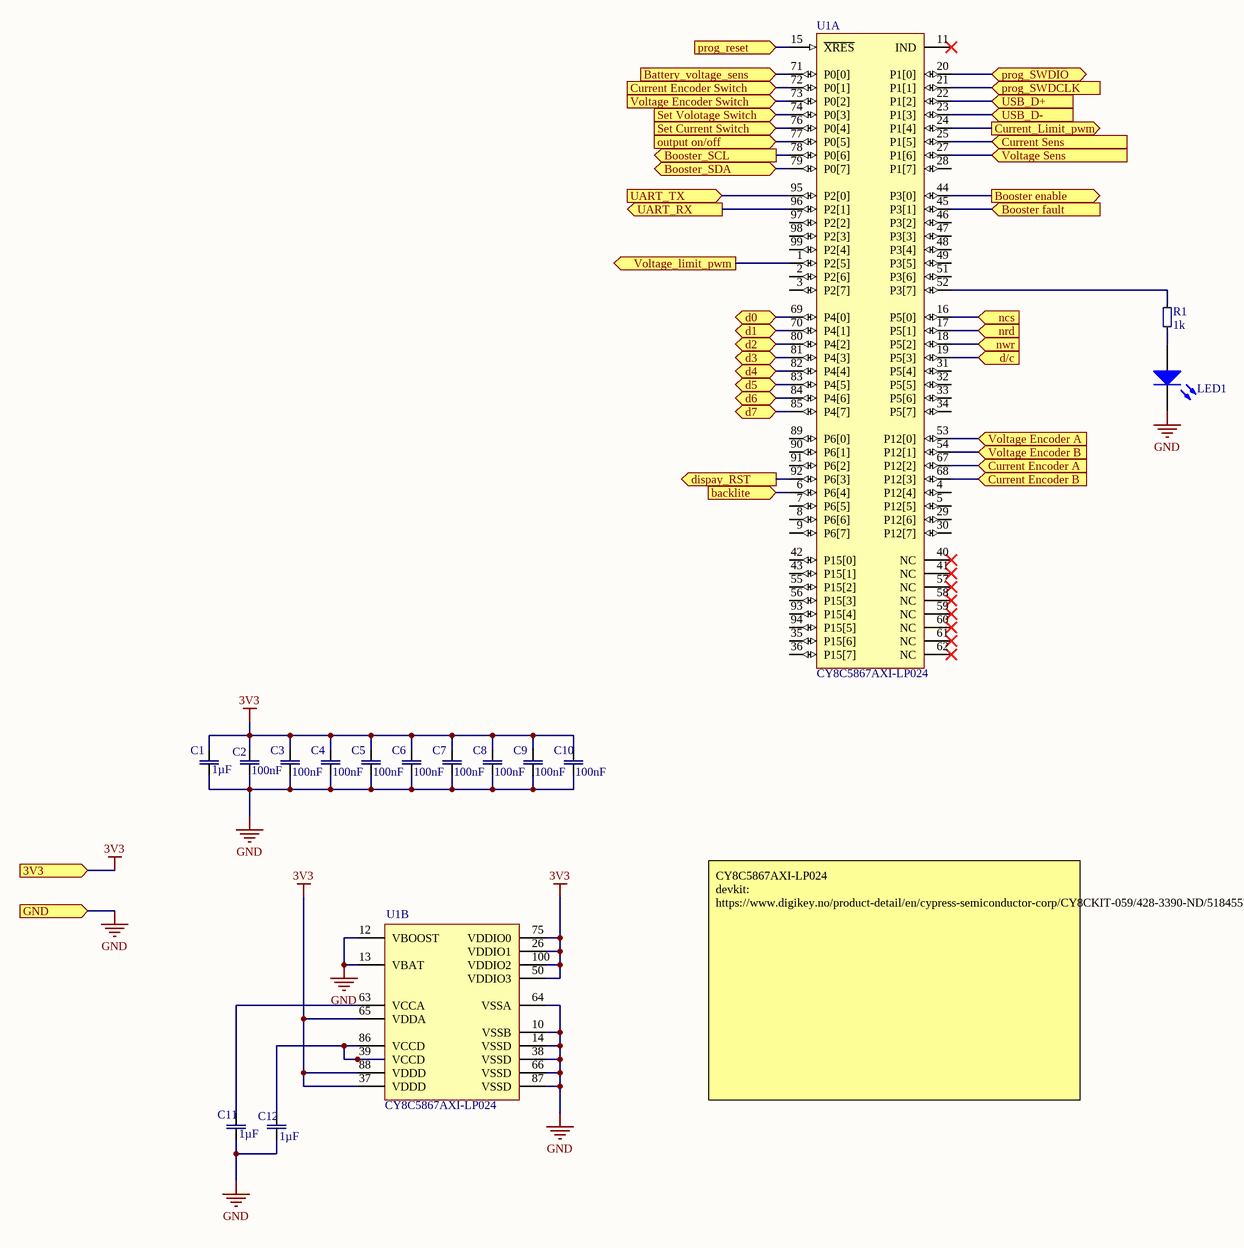
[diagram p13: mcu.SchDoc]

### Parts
C1  Capacitance: 1µF  [CAP0805]  (hidden comment: CL21B105KBFNNNG)
C2  Capacitance: 100nF  [cap0402]  (hidden comment: GRM155R71H104ME14D)
C3  Capacitance: 100nF  [cap0402]  (hidden comment: GRM155R71H104ME14D)
C4  Capacitance: 100nF  [cap0402]  (hidden comment: GRM155R71H104ME14D)
C5  Capacitance: 100nF  [cap0402]  (hidden comment: GRM155R71H104ME14D)
C6  Capacitance: 100nF  [cap0402]  (hidden comment: GRM155R71H104ME14D)
C7  Capacitance: 100nF  [cap0402]  (hidden comment: GRM155R71H104ME14D)
C8  Capacitance: 100nF  [cap0402]  (hidden comment: GRM155R71H104ME14D)
C9  Capacitance: 100nF  [cap0402]  (hidden comment: GRM155R71H104ME14D)
C10  Capacitance: 100nF  [cap0402]  (hidden comment: GRM155R71H104ME14D)
C11  Capacitance: 1µF  [CAP0805]  (hidden comment: CL21B105KBFNNNG)
C12  Capacitance: 1µF  [CAP0805]  (hidden comment: CL21B105KBFNNNG)
LED1  150080BS75000  [0805_A]  (value not drawn)
R1  Resistance: 1k  [SMD_0402(1005)_M]  (hidden comment: RC0402FR-071KL)
U1  CY8C5867AXI-LP024  [CYP-AX100_M]  (parts A,B of 2)

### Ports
3V3 (in), backlite (in), Battery_voltage_sens (in), Booster enable (out), Booster fault (in), Booster_SCL (out), Booster_SDA (bidir), Current Encoder A (in), Current Encoder B (in), Current Encoder Switch (in), Current Sens (in), Current_Limit_pwm (out), d0 (bidir), d1 (bidir), d2 (bidir), d3 (bidir), d4 (bidir), d5 (bidir), d6 (bidir), d7 (bidir), d/c (in), dispay_RST (out), GND (in), ncs (in), nrd (in), nwr (in), output on/off (in), prog_reset (in), prog_SWDCLK (in), prog_SWDIO (bidir), Set Current Switch (in), Set Volotage Switch (in), UART_RX (out), UART_TX (in), USB_D+ (in), USB_D- (in), Voltage Encoder A (in), Voltage Encoder B (in), Voltage Encoder Switch (in), Voltage Sens (in), Voltage_limit_pwm (out)

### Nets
3V3: C1.2 C2.2 C3.2 C4.2 C5.2 C6.2 C7.2 C8.2 C9.2 C10.2 U1.26(VDDIO1) U1.37(VDDD) U1.50(VDDIO3) U1.65(VDDA) U1.75(VDDIO0) U1.88(VDDD) U1.100(VDDIO2) ; port 3V3
GND: C1.1 C2.1 C3.1 C4.1 C5.1 C6.1 C7.1 C8.1 C9.1 C10.1 C11.1 C12.1 LED1.1(K) U1.10(VSSB) U1.12(VBOOST) U1.13(VBAT) U1.14(VSSD) U1.38(VSSD) U1.64(VSSA) U1.66(VSSD) U1.87(VSSD) ; port GND  [project net SGND]
NetC11_2: C11.2 U1.63(VCCA)
NetC12_2: C12.2 U1.39(VCCD) U1.86(VCCD)
NetC32_2: U1.67(P12[2]) ; port Current Encoder A
NetC33_1: U1.68(P12[3]) ; port Current Encoder B
NetC34_2: U1.53(P12[0]) ; port Voltage Encoder A
NetC35_1: U1.54(P12[1]) ; port Voltage Encoder B
NetCN2_1: U1.20(P1[0]) ; port prog_SWDIO
NetCN2_2: U1.21(P1[1]) ; port prog_SWDCLK
NetCN2_3: U1.15(~{XRES}) ; port prog_reset
NetCN2_6: U1.95(P2[0]) ; port UART_TX
NetCN2_7: U1.96(P2[1]) ; port UART_RX
NetDisplay1_23: U1.16(P5[0]) ; port ncs
NetDisplay1_24: U1.19(P5[3]) ; port d/c
NetDisplay1_25: U1.18(P5[2]) ; port nwr
NetDisplay1_26: U1.17(P5[1]) ; port nrd
NetDisplay1_27: U1.92(P6[3]) ; port dispay_RST
NetDisplay1_28: U1.6(P6[4]) ; port backlite
NetDisplay1_33: U1.69(P4[0]) ; port d0
NetDisplay1_34: U1.70(P4[1]) ; port d1
NetDisplay1_35: U1.80(P4[2]) ; port d2
NetDisplay1_36: U1.81(P4[3]) ; port d3
NetDisplay1_37: U1.82(P4[4]) ; port d4
NetDisplay1_38: U1.83(P4[5]) ; port d5
NetDisplay1_39: U1.84(P4[6]) ; port d6
NetDisplay1_40: U1.85(P4[7]) ; port d7
NetLED1_2: LED1.2(A) R1.1
NetR1_2: R1.2 U1.52(P3[7])
NetR4_1: U1.71(P0[0]) ; port Battery_voltage_sens
NetR7_1: U1.78(P0[6]) ; port Booster_SCL
NetR8_1: U1.79(P0[7]) ; port Booster_SDA
NetR9_1: U1.44(P3[0]) ; port Booster enable
NetR21_1: U1.24(P1[4]) ; port Current_Limit_pwm
NetR29_2: U1.22(P1[2]) ; port USB_D+
NetR31_2: U1.23(P1[3]) ; port USB_D-
NetR32_1: U1.27(P1[6]) ; port Voltage Sens
NetR49_1: U1.1(P2[5]) ; port Voltage_limit_pwm
NetSW2_1: U1.72(P0[1]) ; port Current Encoder Switch
NetSW3_1: U1.76(P0[4]) ; port Set Current Switch
NetSW4_1: U1.73(P0[2]) ; port Voltage Encoder Switch
NetSW5_1: U1.74(P0[3]) ; port Set Volotage Switch
NetSW6_1: U1.77(P0[5]) ; port output on/off
NetU1_25: U1.25(P1[5]) ; port Current Sens
NetU1_45: U1.45(P3[1]) ; port Booster fault

Not connected (* = marked no-connect by the designer): U1 2(P2[6]) 3(P2[7]) 4(P12[4]) 5(P12[5]) 7(P6[5]) 8(P6[6]) 9(P6[7]) 11(IND)* 28(P1[7]) 29(P12[6]) 30(P12[7]) 31(P5[4]) 32(P5[5]) 33(P5[6]) 34(P5[7]) 35(P15[6]) 36(P15[7]) 40(NC)* 41(NC)* 42(P15[0]) 43(P15[1]) 46(P3[2]) 47(P3[3]) 48(P3[4]) 49(P3[5]) 51(P3[6]) 55(P15[2]) 56(P15[3]) 57(NC)* 58(NC)* 59(NC)* 60(NC)* 61(NC)* 62(NC)* 89(P6[0]) 90(P6[1]) 91(P6[2]) 93(P15[4]) 94(P15[5]) 97(P2[2]) 98(P2[3]) 99(P2[4])

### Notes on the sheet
- CY8C5867AXI-LP024
  devkit: https://www.digikey.no/product-detail/en/cypress-semiconductor-corp/CY8CKIT-059/428-3390-ND/5184557

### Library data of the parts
C1 C11 C12 = CMP-0001-00012-4: as C37 on sheet LDO
C2-C10 = CMP-0001-00001-8: as C14 on sheet battery
LED1 = CMP-00002-1: as LED2 on sheet battery
R1 = CMP-001-0000-7: as R2 on sheet battery
U1 = CMP-00001-4: IC MCU 32BIT 128KB FLASH 100TQFP; Min Supply Voltage: 1.71V; RAM Size: 32KB; Max Frequency: 67MHz; Data Bus Width: 32b; Peripherals: POR,PWM,WDT,DMA,LCD,CapSense; Number of I/Os: 62; Core Architecture: ARM; Interface: I2C,SPI,UART,USB,USART,LIN; Oscillator Type: Internal; Number of Timers/Counters: 4; Max Supply Voltage: 5.5V; Number of ADC Channels: 2

## Sheet Display.SchDoc
size A3
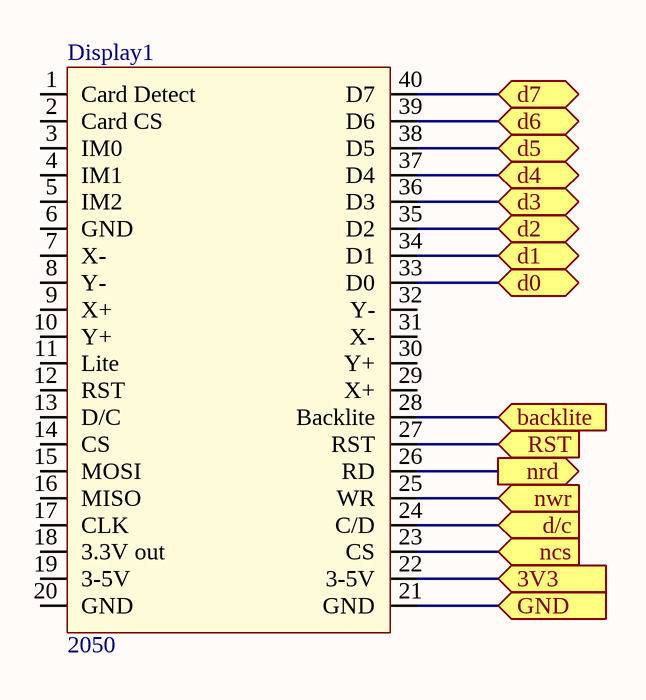
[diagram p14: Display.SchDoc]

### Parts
Display1  2050  [2050-Footprint-1]

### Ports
3V3 (in), backlite (in), d0 (bidir), d1 (bidir), d2 (bidir), d3 (bidir), d4 (bidir), d5 (bidir), d6 (bidir), d7 (bidir), d/c (in), GND (in), ncs (in), nrd (out), nwr (in), RST (in)

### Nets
3V3: Display1.22(3-5V) ; port 3V3
SGND: Display1.21(GND) ; port GND
NetDisplay1_23: Display1.23(CS) ; port ncs
NetDisplay1_24: Display1.24(C/D) ; port d/c
NetDisplay1_25: Display1.25(WR) ; port nwr
NetDisplay1_26: Display1.26(RD) ; port nrd
NetDisplay1_27: Display1.27(RST) ; port RST
NetDisplay1_28: Display1.28(Backlite) ; port backlite
NetDisplay1_33: Display1.33(D0) ; port d0
NetDisplay1_34: Display1.34(D1) ; port d1
NetDisplay1_35: Display1.35(D2) ; port d2
NetDisplay1_36: Display1.36(D3) ; port d3
NetDisplay1_37: Display1.37(D4) ; port d4
NetDisplay1_38: Display1.38(D5) ; port d5
NetDisplay1_39: Display1.39(D6) ; port d6
NetDisplay1_40: Display1.40(D7) ; port d7

Not connected (* = marked no-connect by the designer): Display1 1(Card_Detect) 2(Card_CS) 3(IM0) 4(IM1) 5(IM2) 6(GND) 7(X-) 8(Y-) 9(X+) 10(Y+) 11(Lite) 12(RST) 13(D/C) 14(CS) 15(MOSI) 16(MISO) 17(CLK) 18(3.3V_out) 19(3-5V) 20(GND) 29(X+) 30(Y+) 31(X-) 32(Y-)

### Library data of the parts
Display1 = CMP-ROOT-00015-5: 3.5" TFT 320X480 TOUCHSCREEN; Backlight Type: LED; Diagonal Size: 3.5inch; Touchscreen: Resistive; Resolution (height): 480pixel; Resolution (width): 320pixel; Interface: Serial,Parallel

## Sheet programmer.SchDoc
size A3
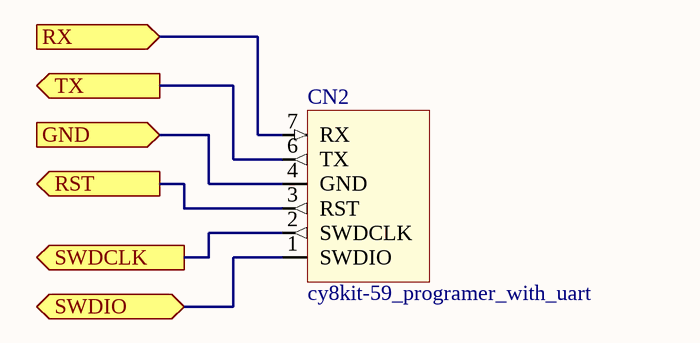
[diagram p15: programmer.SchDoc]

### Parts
CN2  cy8kit-59_programer_with_uart  [PR20203VBNN-Footprint-1]

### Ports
GND (in), RST (out), RX (in), SWDCLK (out), SWDIO (bidir), TX (out)

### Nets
SGND: CN2.4(GND) ; port GND
NetCN2_1: CN2.1(SWDIO) ; port SWDIO
NetCN2_2: CN2.2(SWDCLK) ; port SWDCLK
NetCN2_3: CN2.3(RST) ; port RST
NetCN2_6: CN2.6(TX) ; port TX
NetCN2_7: CN2.7(RX) ; port RX

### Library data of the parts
CN2 = CMP-ROOT-0002-3: CONN HDR 5POS 0.1 GOLD PCB; Pitch: 0.1inch; System: Connector; Connector Type: Header,Socket; Number of Positions: 5

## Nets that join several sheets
3V3: LDO (C38.2 U4.5), usb_isolator (C48.1 R25.2 U6.16), Booster (R7.2 R8.2 R9.2), linear_regulator (5 pins), pwm_to_analog (U2.5 U2.6), knobs (R45.2 R51.2 R52.2 R53.2), mcu (17 pins), Display (Display1.22)
PGND: LDO (C37.1 C38.1 R19.1 U4.2), battery (7 pins), usb_isolator (7 pins), Driver (CN3.1), Booster (14 pins), linear_regulator (8 pins)
SGND: LDO (R19.2), battery (R5.1), Driver (R33.1 R36.1 R37.1 R38.1), Booster (7 pins), pwm_to_analog (C39.1 C40.1 C41.1 U2.2), pwm_to_analog_w_gain (C52.1 C53.1 C54.1 U10.2), knobs (15 pins), mcu (21 pins), Display (Display1.21), programmer (CN2.4)
5V: battery (C13.2 C14.2 R2.2 U3.4), usb_isolator (C44.2 ISO1.8)
NetC32_2: knobs (C32.2 R16.1), mcu (U1.67)
NetC33_1: knobs (C33.1 R17.1), mcu (U1.68)
NetC34_2: knobs (C34.2 R18.1), mcu (U1.53)
NetC35_1: knobs (C35.1 R44.1), mcu (U1.54)
NetC49_2: Booster (R6.1 U5.13), linear_regulator (C49.2 U7.3), pwm_to_analog_w_gain (U10.5 U10.6)
NetCN1_1: Driver (CN1.1 R32.2), linear_regulator (D1.1 Q3.2 R39.2)
NetCN2_1: mcu (U1.20), programmer (CN2.1)
NetCN2_2: mcu (U1.21), programmer (CN2.2)
NetCN2_3: mcu (U1.15), programmer (CN2.3)
NetCN2_6: mcu (U1.95), programmer (CN2.6)
NetCN2_7: mcu (U1.96), programmer (CN2.7)
NetDisplay1_23: mcu (U1.16), Display (Display1.23)
NetDisplay1_24: mcu (U1.19), Display (Display1.24)
NetDisplay1_25: mcu (U1.18), Display (Display1.25)
NetDisplay1_26: mcu (U1.17), Display (Display1.26)
NetDisplay1_27: mcu (U1.92), Display (Display1.27)
NetDisplay1_28: mcu (U1.6), Display (Display1.28)
NetDisplay1_33: mcu (U1.69), Display (Display1.33)
NetDisplay1_34: mcu (U1.70), Display (Display1.34)
NetDisplay1_35: mcu (U1.80), Display (Display1.35)
NetDisplay1_36: mcu (U1.81), Display (Display1.36)
NetDisplay1_37: mcu (U1.82), Display (Display1.37)
NetDisplay1_38: mcu (U1.83), Display (Display1.38)
NetDisplay1_39: mcu (U1.84), Display (Display1.39)
NetDisplay1_40: mcu (U1.85), Display (Display1.40)
NetJ1_A6: usb (J1.A6 J1.B6), usb_isolator (R28.1)
NetJ1_A7: usb (J1.A7 J1.B7), usb_isolator (R30.1)
NetR4_1: battery (R4.1 R5.2), mcu (U1.71)
NetR7_1: Booster (R7.1 U5.5), mcu (U1.78)
NetR8_1: Booster (R8.1 U5.6), mcu (U1.79)
NetR9_1: Booster (R9.1 U5.4), mcu (U1.44)
NetR21_1: pwm_to_analog (R21.1), mcu (U1.24)
NetR29_2: usb_isolator (R29.2), mcu (U1.22)
NetR31_2: usb_isolator (R31.2), mcu (U1.23)
NetR32_1: Driver (R32.1 R33.2), mcu (U1.27)
NetR36_2: Driver (R36.2 R37.2 R38.2), pwm_to_analog_w_gain (R48.1 U10.3)
NetR41_2: linear_regulator (R41.2), pwm_to_analog_w_gain (R48.2 U10.4)
NetR49_1: pwm_to_analog_w_gain (R49.1), mcu (U1.1)
NetSW2_1: knobs (SW2.1), mcu (U1.72)
NetSW3_1: knobs (SW3.1), mcu (U1.76)
NetSW4_1: knobs (SW4.1), mcu (U1.73)
NetSW5_1: knobs (SW5.1), mcu (U1.74)
NetSW6_1: knobs (SW6.1), mcu (U1.77)
NetU1_25: Booster (U5.16), linear_regulator (U9.1), mcu (U1.25)
NetU1_45: Booster (U5.14), mcu (U1.45)
NetU2_3: linear_regulator (U9.3), pwm_to_analog (U2.3 U2.4)
USB_GND: usb (C42.1 J1.A1-B12 J1.B1-A12 R20.1), usb_isolator (7 pins)
VBAT: LDO (C37.2 U4.1 U4.3), battery (R4.2 SW1.3), Booster (7 pins)
VBUS: usb (J1.A4-B9 J1.B4-A9), usb_isolator (5 pins)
